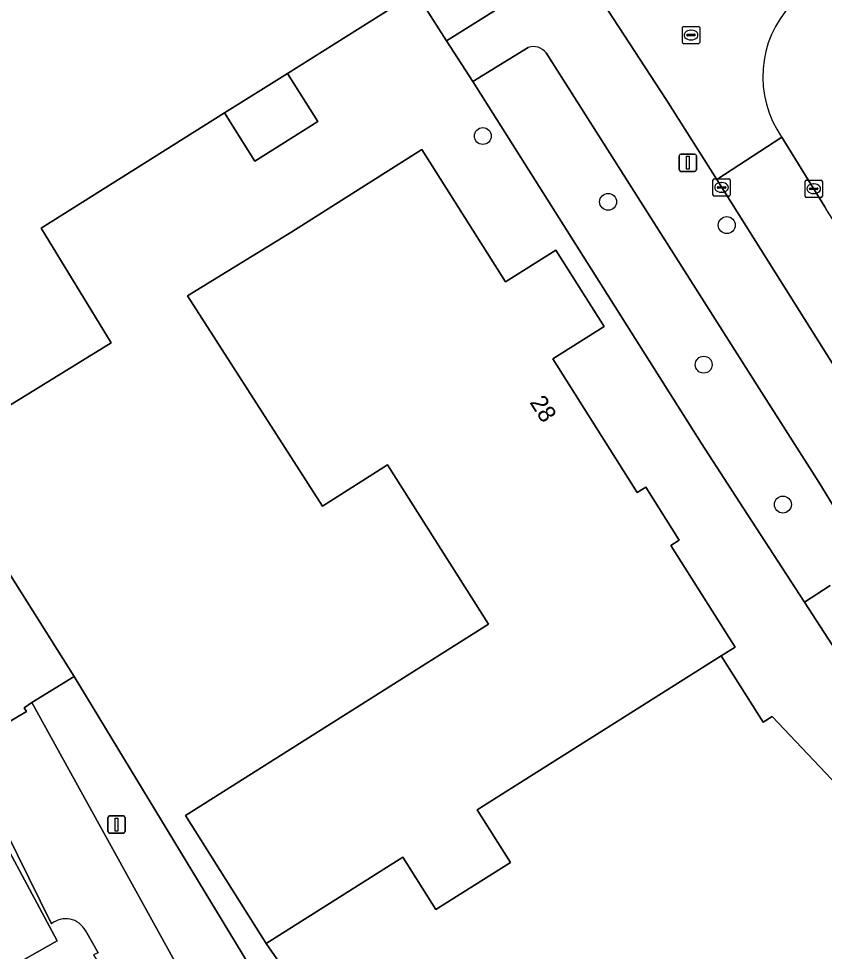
# Model space of a CAD drawing. Extents: x 162344 to 162869, y 381217 to 381818.
# Drawn here: x 162549.4 to 162596, y 381421.8 to 381475.8 of the extents above; entities that cross this region are included whole.
import ezdxf

# ---------------------------------------------------------------- set-up
doc = ezdxf.new("R2010")
doc.units = 0
for name, color, linetype in [('IMGEO_Boom', 7, 'Continuous'), ('IMGEO_Erf', 7, 'Continuous'), ('IMGEO_Groenvoorziening', 7, 'Continuous'), ('IMGEO_Hek', 7, 'Continuous'), ('IMGEO_Kolk', 7, 'Continuous'), ('IMGEO_Lichtmast', 7, 'Continuous'), ('IMGEO_Pand', 7, 'Continuous'), ('IMGEO_Pand_nummerreeks', 7, 'Continuous'), ('IMGEO_Parkeervlak_open', 7, 'Continuous'), ('IMGEO_Rijbaan_lokaal_gesloten', 7, 'Continuous'), ('IMGEO_Rijbaan_lokaal_open', 7, 'Continuous'), ('IMGEO_Rioolput', 7, 'Continuous'), ('IMGEO_Voetpad_open', 7, 'Continuous')]:
    doc.layers.add(name, color=color, linetype=linetype)

msp = doc.modelspace()

# ---------------------------------------------------------------- linework, layer by layer
at = {"layer": 'IMGEO_Boom'}
for centre in [(162576.241, 381468.971), (162583.478, 381465.169), (162590.335, 381463.822), (162589.003, 381455.751), (162593.579, 381447.66)]:
    msp.add_circle(centre, 0.489, dxfattribs=at)
at = {"layer": 'IMGEO_Erf'}
for points in [[(162622.037, 381407.841), (162605.841, 381425.165), (162603.922, 381427.994), (162596.425, 381439.548), (162594.828, 381442.012), (162591.287, 381447.468), (162588.885, 381451.187), (162575.654, 381472.131), (162574.139, 381474.467), (162572.367, 381477.268), (162564.943, 381472.596), (162566.7, 381469.803), (162563.061, 381467.513), (162561.304, 381470.306), (162550.724, 381463.648), (162554.763, 381457.01), (162544.461, 381450.664), (162552.634, 381437.722), (162563.756, 381419.355)], [(162565.124, 381420.252), (162563.715, 381422.29), (162559.051, 381429.674), (162576.572, 381440.738), (162570.733, 381449.951), (162566.971, 381447.566), (162559.166, 381459.722), (162565.194, 381463.435), (162572.717, 381468.186)], [(162572.717, 381468.186), (162577.548, 381460.536), (162580.455, 381462.371), (162583.242, 381457.957), (162580.287, 381456.091), (162585.166, 381448.364), (162585.665, 381448.66), (162587.593, 381445.608), (162587.102, 381445.298), (162590.813, 381439.422), (162590.01, 381438.915), (162592.432, 381435.079), (162592.952, 381435.408), (162603.272, 381424.519), (162602.633, 381423.885), (162603.56, 381422.951), (162608.827, 381417.399)]]:
    msp.add_lwpolyline(points, dxfattribs=at)
at = {"layer": 'IMGEO_Groenvoorziening'}
for points in [[(162547.898, 381434.544), (162549.879, 381435.692), (162549.738, 381435.916), (162550.185, 381436.215), (162552.634, 381437.722), (162544.461, 381450.664), (162554.763, 381457.01), (162550.724, 381463.648), (162561.304, 381470.306), (162564.943, 381472.596), (162572.367, 381477.268), (162567.67, 381484.693), (162566.612, 381486.366), (162560.659, 381495.777), (162538.071, 381484.442)], [(162571.491, 381487.11), (162569.801, 381486.041), (162567.67, 381484.693), (162572.367, 381477.268), (162574.139, 381474.467), (162576.301, 381475.822), (162577.344, 381476.475)], [(162578.867, 381474.091), (162577.756, 381473.413), (162575.654, 381472.131), (162588.885, 381451.187), (162591.287, 381447.468), (162594.828, 381442.012), (162596.314, 381442.992)], [(162597.498, 381445.923), (162595.651, 381448.964), (162592.214, 381454.371), (162579.893, 381473.779)], [(162552.634, 381437.722), (162550.185, 381436.215), (162562.598, 381413.707)], [(162565.33, 381404.909), (162567.107, 381391.628), (162568.071, 381391.773), (162568.257, 381391.801), (162564.593, 381413.622), (162563.756, 381419.355), (162552.634, 381437.722)], [(162551.316, 381423.428), (162546.716, 381432.738), (162528.414, 381424.756), (162527.509, 381427.397), (162546.558, 381435.544)], [(162554.012, 381421.751), (162553.277, 381423.033)]]:
    msp.add_lwpolyline(points, dxfattribs=at)
msp.add_lwpolyline([(162545.47, 381421.311), (162541.728, 381428.198), (162546.973, 381431.115), (162551.651, 381422.432), (162536.054, 381413.606), (162534.87, 381415.667)], close=True, dxfattribs=at)
for centre, radius, start, end in [((162579.162, 381473.22), 0.92, 37.4362, 108.7354), ((162552.132, 381422.414), 1.302, 28.3933, 128.8296)]:
    msp.add_arc(centre, radius, start, end, dxfattribs=at)
at = {"layer": 'IMGEO_Hek'}
msp.add_lwpolyline([(162552.634, 381437.722), (162550.185, 381436.215)], dxfattribs=at)
at = {"layer": 'IMGEO_Kolk'}
for p, q in [((162589.537, 381465.574), (162589.537, 381466.426)), ((162589.612, 381466.5), (162590.464, 381466.5)), ((162590.538, 381466.426), (162590.538, 381465.574)), ((162594.86, 381465.497), (162594.86, 381466.349)), ((162594.935, 381466.423), (162595.787, 381466.423)), ((162595.861, 381466.349), (162595.861, 381465.497)), ((162589.796, 381465.994), (162589.796, 381466.006)), ((162590.234, 381465.957), (162589.836, 381465.957)), ((162589.839, 381466.043), (162590.237, 381466.043)), ((162590.025, 381466.28), (162590.05, 381466.28)), ((162590.28, 381466.006), (162590.28, 381465.994)), ((162595.119, 381465.917), (162595.119, 381465.929)), ((162595.557, 381465.88), (162595.159, 381465.88)), ((162595.162, 381465.966), (162595.56, 381465.966)), ((162595.348, 381466.203), (162595.373, 381466.203)), ((162595.603, 381465.929), (162595.603, 381465.917)), ((162590.464, 381465.5), (162589.612, 381465.5)), ((162590.048, 381465.72), (162590.023, 381465.72)), ((162595.787, 381465.423), (162594.935, 381465.423)), ((162595.371, 381465.643), (162595.346, 381465.643))]:
    msp.add_line(p, q, dxfattribs=at)
for points in [[(162589.537, 381465.574), (162589.537, 381466.426)], [(162589.612, 381466.5), (162590.464, 381466.5)], [(162590.538, 381466.426), (162590.538, 381465.574)], [(162594.86, 381465.497), (162594.86, 381466.349)], [(162594.935, 381466.423), (162595.787, 381466.423)], [(162595.861, 381466.349), (162595.861, 381465.497)], [(162590.464, 381465.5), (162589.612, 381465.5)], [(162595.787, 381465.423), (162594.935, 381465.423)]]:
    msp.add_lwpolyline(points, dxfattribs=at)
for centre, radius, start, end in [((162589.614, 381466.424), 0.0765, 91.552, 178.448), ((162589.614, 381466.424), 0.0765, 91.552, 178.448), ((162590.462, 381466.424), 0.0765, 1.552, 88.448), ((162590.462, 381466.424), 0.0765, 1.552, 88.448), ((162594.937, 381466.347), 0.0765, 91.552, 178.448), ((162594.937, 381466.347), 0.0765, 91.552, 178.448), ((162595.785, 381466.347), 0.0765, 1.552, 88.448), ((162595.785, 381466.347), 0.0765, 1.552, 88.448), ((162589.836, 381466.003), 0.0403, 85.8775, 175.7526), ((162589.833, 381465.993), 0.0366, 178.938, 274.7102), ((162590.237, 381466), 0.043, 264.8664, 352.4533), ((162590.241, 381466.005), 0.0386, 1.7309, 96.639), ((162595.159, 381465.926), 0.0403, 85.8775, 175.7526), ((162595.156, 381465.916), 0.0366, 178.938, 274.7102), ((162595.56, 381465.923), 0.043, 264.8664, 352.4533), ((162595.564, 381465.928), 0.0386, 1.7309, 96.639), ((162589.614, 381465.576), 0.0765, 181.552, 268.448), ((162589.614, 381465.576), 0.0765, 181.552, 268.448), ((162590.462, 381465.576), 0.0765, 271.552, 358.448), ((162590.462, 381465.576), 0.0765, 271.552, 358.448), ((162594.937, 381465.499), 0.0765, 181.552, 268.448), ((162594.937, 381465.499), 0.0765, 181.552, 268.448), ((162595.785, 381465.499), 0.0765, 271.552, 358.448), ((162595.785, 381465.499), 0.0765, 271.552, 358.448)]:
    msp.add_arc(centre, radius, start, end, dxfattribs=at)
for centre, major_axis, ratio, start_param, end_param in [((162590.024, 381466), (-0.387, 0.002), 0.722429, 4.712389, 7.853982), ((162590.049, 381466), (-0.39, 0.002), 0.717154, 1.570796, 4.712389), ((162595.347, 381465.923), (-0.387, 0.002), 0.722429, 4.712389, 7.853982), ((162595.372, 381465.923), (-0.39, 0.002), 0.717154, 1.570796, 4.712389)]:
    msp.add_ellipse(centre, major_axis=major_axis, ratio=ratio, start_param=start_param, end_param=end_param, dxfattribs=at)
at = {"layer": 'IMGEO_Lichtmast'}
for p, q in [((162587.69, 381467.924), (162588.48, 381467.924)), ((162588.48, 381467.924), (162587.69, 381467.924)), ((162587.59, 381467.024), (162587.59, 381467.824)), ((162587.59, 381467.824), (162587.59, 381467.024)), ((162588.58, 381467.824), (162588.58, 381467.024)), ((162588.58, 381467.024), (162588.58, 381467.824)), ((162588.48, 381466.924), (162587.69, 381466.924)), ((162587.69, 381466.924), (162588.48, 381466.924)), ((162554.676, 381429.662), (162555.466, 381429.662)), ((162555.466, 381429.662), (162554.676, 381429.662)), ((162554.576, 381428.762), (162554.576, 381429.562)), ((162554.576, 381429.562), (162554.576, 381428.762)), ((162555.566, 381429.562), (162555.566, 381428.762)), ((162555.566, 381428.762), (162555.566, 381429.562)), ((162555.466, 381428.662), (162554.676, 381428.662)), ((162554.676, 381428.662), (162555.466, 381428.662))]:
    msp.add_line(p, q, dxfattribs=at)
for points in [[(162588.01, 381467.799), (162588.16, 381467.799), (162588.16, 381467.049), (162588.01, 381467.049), (162588.01, 381467.799)], [(162554.996, 381429.537), (162555.146, 381429.537), (162555.146, 381428.787), (162554.996, 381428.787), (162554.996, 381429.537)]]:
    msp.add_lwpolyline(points, dxfattribs=at)
for centre, start, end in [((162587.69, 381467.824), 90, 180), ((162587.69, 381467.824), 90, 180), ((162588.48, 381467.824), 0, 90), ((162588.48, 381467.824), 360, 90), ((162587.69, 381467.024), 180, 270), ((162587.69, 381467.024), 180, 270), ((162588.48, 381467.024), 270, 0), ((162588.48, 381467.024), 270, 0), ((162554.676, 381429.562), 90, 180), ((162554.676, 381429.562), 90, 180), ((162555.466, 381429.562), 0, 90), ((162555.466, 381429.562), 360, 90), ((162554.676, 381428.762), 180, 270), ((162554.676, 381428.762), 180, 270), ((162555.466, 381428.762), 270, 0), ((162555.466, 381428.762), 270, 0)]:
    msp.add_arc(centre, 0.1, start, end, dxfattribs=at)
at = {"layer": 'IMGEO_Pand'}
for points in [[(162563.061, 381467.513), (162566.7, 381469.803), (162564.943, 381472.596), (162561.304, 381470.306)], [(162587.102, 381445.298), (162587.593, 381445.608), (162585.665, 381448.66), (162585.166, 381448.364), (162580.287, 381456.091), (162583.242, 381457.957), (162580.455, 381462.371), (162577.548, 381460.536), (162572.717, 381468.186), (162565.194, 381463.435), (162559.166, 381459.722), (162566.971, 381447.566), (162570.733, 381449.951), (162576.572, 381440.738), (162559.051, 381429.674), (162563.715, 381422.29), (162571.61, 381427.275), (162573.52, 381424.25), (162577.832, 381426.973), (162575.915, 381430.015), (162590.01, 381438.915), (162590.813, 381439.422)]]:
    msp.add_lwpolyline(points, close=True, dxfattribs=at)
msp.add_lwpolyline([(162608.827, 381417.399), (162603.56, 381422.951), (162602.633, 381423.885), (162603.272, 381424.519), (162592.952, 381435.408), (162592.432, 381435.079), (162590.01, 381438.915), (162575.915, 381430.015), (162577.832, 381426.973), (162573.52, 381424.25), (162571.61, 381427.275), (162563.715, 381422.29), (162565.124, 381420.252)], dxfattribs=at)
at = {"layer": 'IMGEO_Parkeervlak_open'}
msp.add_lwpolyline([(162546.973, 381431.115), (162541.728, 381428.198), (162545.47, 381421.311), (162534.87, 381415.667), (162536.054, 381413.606), (162551.651, 381422.432)], close=True, dxfattribs=at)
at = {"layer": 'IMGEO_Rijbaan_lokaal_gesloten'}
for points in [[(162624.194, 381421.482), (162622.707, 381423.487), (162619.556, 381427.86), (162615.628, 381434.046), (162615.487, 381434.272), (162615.118, 381434.889), (162605.798, 381449.492), (162605.481, 381449.991), (162601.154, 381456.882), (162596.087, 381464.752), (162596.011, 381464.87), (162593.509, 381468.912), (162589.756, 381466.45), (162596.967, 381454.988), (162603.511, 381444.701), (162605.459, 381441.582), (162607.233, 381438.741), (162609.601, 381435.057), (162614.534, 381427.306), (162616.235, 381424.738), (162618.43, 381421.705)], [(162550.185, 381436.215), (162549.738, 381435.916), (162549.879, 381435.692), (162547.898, 381434.544), (162547.779, 381434.758), (162547.291, 381434.43), (162547.44, 381434.134), (162547.525, 381434.003), (162547.8, 381433.443), (162547.509, 381433.329), (162547.598, 381433.122), (162546.716, 381432.738), (162551.316, 381423.428)], [(162562.598, 381413.707), (162550.185, 381436.215)], [(162553.277, 381423.033), (162554.012, 381421.751), (162553.751, 381421.621), (162557.228, 381415.975)]]:
    msp.add_lwpolyline(points, dxfattribs=at)
msp.add_arc((162552.132, 381422.414), 1.302, 28.3933, 128.8296, dxfattribs=at)
at = {"layer": 'IMGEO_Rijbaan_lokaal_open'}
msp.add_lwpolyline([(162583.663, 381484.277), (162583.317, 381484.753), (162583.279, 381484.807), (162579.561, 381482.257), (162586.829, 381471.084), (162589.756, 381466.45), (162593.509, 381468.912)], dxfattribs=at)
msp.add_arc((162598.549, 381472.404), 6.132, 136.9164, 214.7131, dxfattribs=at)
at = {"layer": 'IMGEO_Rioolput'}
for p, q in [((162587.771, 381474.386), (162587.771, 381475.238)), ((162587.846, 381475.312), (162588.698, 381475.312)), ((162588.259, 381475.092), (162588.284, 381475.092)), ((162588.772, 381475.238), (162588.772, 381474.386)), ((162588.03, 381474.806), (162588.03, 381474.818)), ((162588.468, 381474.769), (162588.07, 381474.769)), ((162588.073, 381474.855), (162588.471, 381474.855)), ((162588.282, 381474.532), (162588.257, 381474.532)), ((162588.514, 381474.818), (162588.514, 381474.806)), ((162588.698, 381474.312), (162587.846, 381474.312))]:
    msp.add_line(p, q, dxfattribs=at)
for points in [[(162587.771, 381474.386), (162587.771, 381475.238)], [(162587.846, 381475.312), (162588.698, 381475.312)], [(162588.772, 381475.238), (162588.772, 381474.386)], [(162588.698, 381474.312), (162587.846, 381474.312)]]:
    msp.add_lwpolyline(points, dxfattribs=at)
for centre, radius, start, end in [((162587.848, 381475.236), 0.0765, 91.552, 178.448), ((162587.848, 381475.236), 0.0765, 91.552, 178.448), ((162588.696, 381475.236), 0.0765, 1.552, 88.448), ((162588.696, 381475.236), 0.0765, 1.552, 88.448), ((162588.07, 381474.815), 0.0403, 85.8775, 175.7526), ((162588.067, 381474.805), 0.0366, 178.938, 274.7102), ((162588.471, 381474.812), 0.043, 264.8664, 352.4533), ((162588.475, 381474.817), 0.0386, 1.7309, 96.639), ((162587.848, 381474.388), 0.0765, 181.552, 268.448), ((162587.848, 381474.388), 0.0765, 181.552, 268.448), ((162588.696, 381474.388), 0.0765, 271.552, 358.448), ((162588.696, 381474.388), 0.0765, 271.552, 358.448)]:
    msp.add_arc(centre, radius, start, end, dxfattribs=at)
for centre, major_axis, ratio, start_param, end_param in [((162588.258, 381474.812), (-0.387, 0.002), 0.722429, 4.712389, 7.853982), ((162588.283, 381474.812), (-0.39, 0.002), 0.717154, 1.570796, 4.712389)]:
    msp.add_ellipse(centre, major_axis=major_axis, ratio=ratio, start_param=start_param, end_param=end_param, dxfattribs=at)
at = {"layer": 'IMGEO_Voetpad_open'}
for points in [[(162605.459, 381441.582), (162603.511, 381444.701), (162596.967, 381454.988), (162589.756, 381466.45), (162586.829, 381471.084), (162579.561, 381482.257)], [(162577.344, 381476.475), (162576.301, 381475.822), (162574.139, 381474.467), (162575.654, 381472.131), (162577.756, 381473.413), (162578.867, 381474.091)], [(162579.893, 381473.779), (162592.214, 381454.371), (162595.651, 381448.964), (162597.498, 381445.923), (162601.446, 381439.786), (162606.912, 381431.128)], [(162593.509, 381468.912), (162596.011, 381464.87), (162596.087, 381464.752)], [(162596.314, 381442.992), (162594.828, 381442.012), (162596.425, 381439.548), (162597.449, 381440.223)]]:
    msp.add_lwpolyline(points, dxfattribs=at)
for centre, radius, start, end in [((162598.549, 381472.404), 6.132, 136.9164, 214.7131), ((162579.162, 381473.22), 0.92, 37.4362, 108.7354)]:
    msp.add_arc(centre, radius, start, end, dxfattribs=at)

# ---------------------------------------------------------------- texts
at = {"layer": 'IMGEO_Pand_nummerreeks'}
msp.add_text('28', height=1, rotation=302.2688, dxfattribs=at).set_placement((162578.919, 381453.575))

doc.saveas('drawing.dxf')
